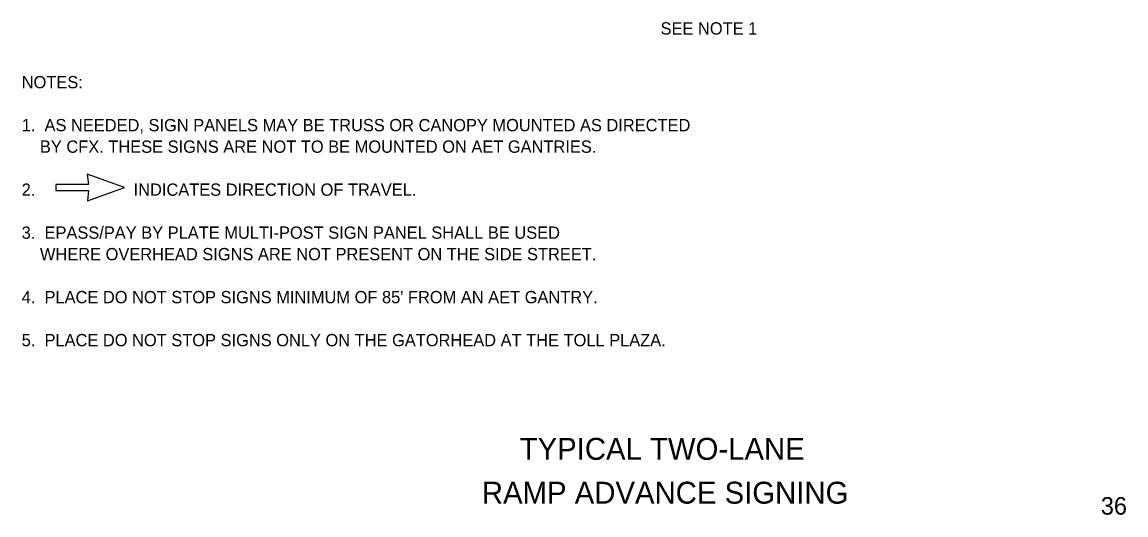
# Model space of a CAD drawing. Extents: x 46672 to 47298, y 5424 to 5742.
# Drawn here: x 47046.4 to 47298.1, y 5434.3 to 5546.6 of the extents above; entities that cross this region are included whole.
import ezdxf

# ---------------------------------------------------------------- set-up
doc = ezdxf.new("R2010")
doc.units = 0
for name, color, linetype in [('GSOutline', 7, 'Continuous'), ('SheetBorder_dp', 7, 'Continuous'), ('TextAlert', 7, 'Continuous'), ('TextShtNo', 7, 'Continuous'), ('TextTitle', 7, 'Continuous')]:
    doc.layers.add(name, color=color, linetype=linetype)

msp = doc.modelspace()

# ---------------------------------------------------------------- linework, layer by layer
at = {"layer": 'TextAlert'}
for p, q in [((47069.76, 5508.92), (47061.26, 5511.93)), ((47061.26, 5511.93), (47061.51, 5509.6)), ((47061.51, 5509.6), (47054.09, 5509.58)), ((47054.09, 5509.58), (47054.09, 5508.21)), ((47061.27, 5505.88), (47069.76, 5508.92)), ((47054.09, 5508.21), (47061.52, 5508.22)), ((47061.52, 5508.22), (47061.27, 5505.88))]:
    msp.add_line(p, q, dxfattribs=at)

# ---------------------------------------------------------------- texts
at = {"layer": 'GSOutline'}
msp.add_text('36', height=4, rotation=360, dxfattribs=at).set_placement((47292.43, 5434.33))
at = {"layer": 'SheetBorder_dp'}
msp.add_text('SEE NOTE 1', height=2.8, dxfattribs=at).set_placement((47192.01, 5543.75))
at = {"layer": 'TextShtNo'}
for s, p in [('    TYPICAL TWO-LANE    ', (47152.45, 5446.83)), ('  RAMP ADVANCE SIGNING  ', (47147.54, 5436.83))]:
    msp.add_text(s, height=5, rotation=360, dxfattribs=at).set_placement(p)
at = {"layer": 'TextTitle'}
for s, p in [('NOTES:', (47046.3, 5531.51)), ('1.  AS NEEDED, SIGN PANELS MAY BE TRUSS OR CANOPY MOUNTED AS DIRECTED', (47046.3, 5521.71)), ('    BY CFX. THESE SIGNS ARE NOT TO BE MOUNTED ON AET GANTRIES.', (47046.3, 5516.81)), ('2.', (47046.3, 5507.01)), ('   INDICATES DIRECTION OF TRAVEL.', (47068.7, 5507.01)), ('3.  EPASS/PAY BY PLATE MULTI-POST SIGN PANEL SHALL BE USED', (47046.3, 5497.21)), ('    WHERE OVERHEAD SIGNS ARE NOT PRESENT ON THE SIDE STREET. ', (47046.3, 5492.31)), ("4.  PLACE DO NOT STOP SIGNS MINIMUM OF 85' FROM AN AET GANTRY.", (47046.3, 5482.51)), ('5.  PLACE DO NOT STOP SIGNS ONLY ON THE GATORHEAD AT THE TOLL PLAZA.', (47046.3, 5472.71))]:
    msp.add_text(s, height=2.8, dxfattribs=at).set_placement(p)

doc.saveas('drawing.dxf')
